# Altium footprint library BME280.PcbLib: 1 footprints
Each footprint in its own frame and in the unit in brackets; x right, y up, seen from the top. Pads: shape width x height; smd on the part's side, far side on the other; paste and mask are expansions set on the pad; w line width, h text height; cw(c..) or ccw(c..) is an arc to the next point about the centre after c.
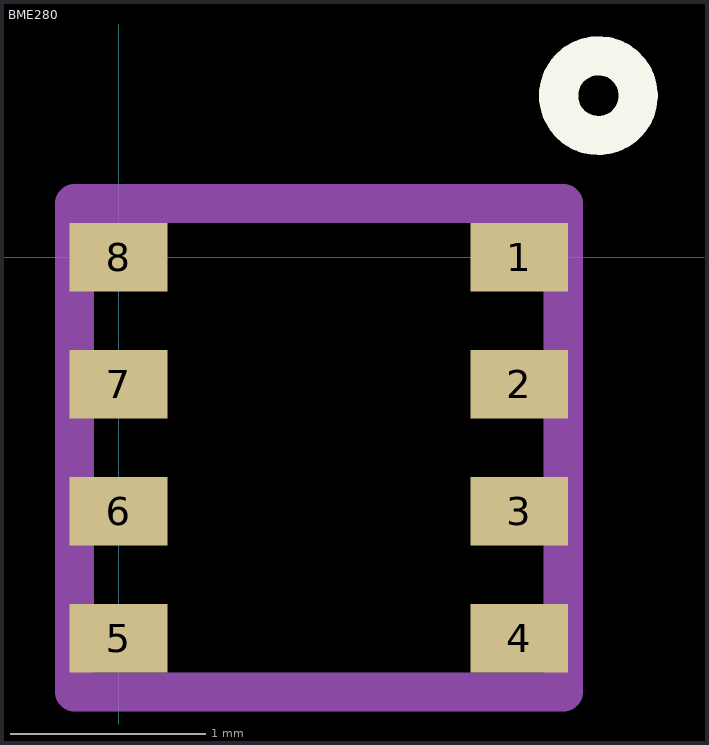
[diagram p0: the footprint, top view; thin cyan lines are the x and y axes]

## BME280 [mm]
pads (8):
  rect 0.5x0.35 smd: 1(2.05,0) 2(2.05,-0.65) 3(2.05,-1.3) 4(2.05,-1.95) 5(0,-1.95) 6(0,-1.3) 7(0,-0.65) 8(0,0)
Top Overlay:
  circle w0.2: c2.455,0.827 r0.204
Mechanical 15:
  lines w0.2: -0.225,-2.225 2.275,-2.225 2.275,0.275 -0.225,0.275 -0.225,-2.225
